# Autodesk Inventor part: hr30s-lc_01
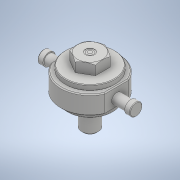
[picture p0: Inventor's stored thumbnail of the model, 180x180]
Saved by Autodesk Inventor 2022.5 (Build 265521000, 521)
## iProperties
Part Number: hr30s-lc_01
Material: 一般
Document SubType Name: Modeling
Designer: ImaoCorp
Density: 1 g/cm^3
Appearance: 既定
Author: ImaoCorp
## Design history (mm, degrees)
feature "hr30s-lc_01"
node "ソリッド1"
